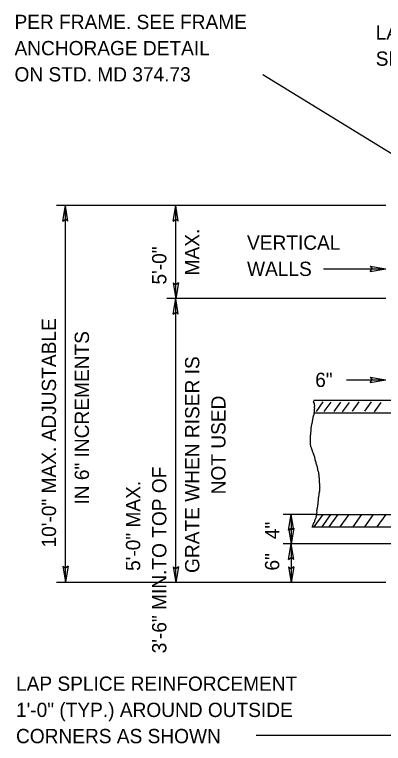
# Model space of a CAD drawing. Extents: x 9.6 to 16.8, y 2.2 to 12.2.
# Drawn here: x 9.55 to 11.1, y 6.199 to 9.259 of the extents above; entities that cross this region are included whole.
import ezdxf

# ---------------------------------------------------------------- set-up
doc = ezdxf.new("R2010")
doc.units = 0
for name, color, linetype in [('DETL-DIMS', 7, 'Continuous'), ('DETL-LINE', 7, 'Continuous'), ('DETL-NOTE', 7, 'Continuous'), ('DETL-PATT', 7, 'Continuous')]:
    doc.layers.add(name, color=color, linetype=linetype)

msp = doc.modelspace()

# ---------------------------------------------------------------- linework, layer by layer
at = {"layer": 'DETL-DIMS'}
for p, q in [((10.5932, 9.008), (11.2062, 8.6311)), ((11.1096, 8.4572), (9.7269, 8.4572)), ((9.7526, 8.3914), (9.7637, 8.4572)), ((9.7745, 8.3913), (9.7637, 8.4572)), ((9.7637, 6.8778), (9.7637, 8.4572)), ((10.2162, 8.3914), (10.2273, 8.4572)), ((10.2382, 8.3913), (10.2273, 8.4572)), ((10.2273, 8.0667), (10.2273, 8.4572)), ((9.7526, 8.3914), (9.7636, 8.3996)), ((9.7745, 8.3913), (9.7636, 8.3996)), ((10.2162, 8.3914), (10.2272, 8.3996)), ((10.2382, 8.3913), (10.2272, 8.3996)), ((11.0438, 8.2024), (11.1096, 8.1915)), ((11.0438, 8.2024), (11.052, 8.1915)), ((10.8477, 8.1915), (11.1096, 8.1915)), ((11.0438, 8.1805), (11.1096, 8.1915)), ((11.0438, 8.1805), (11.052, 8.1915)), ((10.2165, 8.1327), (10.2273, 8.0667)), ((10.2165, 8.1327), (10.2275, 8.1244)), ((10.2384, 8.1326), (10.2273, 8.0667)), ((10.2384, 8.1326), (10.2275, 8.1244)), ((11.1096, 8.0667), (10.1904, 8.0667)), ((10.2162, 8.0009), (10.2273, 8.0667)), ((10.2382, 8.0008), (10.2273, 8.0667)), ((10.2273, 6.8747), (10.2273, 8.0667)), ((10.2162, 8.0009), (10.2272, 8.0091)), ((10.2382, 8.0008), (10.2272, 8.0091)), ((10.9452, 7.7256), (11.1096, 7.7253)), ((11.0437, 7.7144), (11.052, 7.7254)), ((11.0437, 7.7144), (11.1096, 7.7253)), ((11.0438, 7.7364), (11.1096, 7.7253)), ((11.0438, 7.7364), (11.052, 7.7254)), ((10.8178, 7.1604), (10.6784, 7.1604)), ((10.7015, 7.0945), (10.7126, 7.1604)), ((10.7126, 7.1604), (10.7126, 7.0371)), ((10.7235, 7.0944), (10.7126, 7.1604)), ((10.7015, 7.0945), (10.7125, 7.1027)), ((10.7018, 7.1031), (10.7126, 7.0371)), ((10.7018, 7.1031), (10.7127, 7.0947)), ((10.7235, 7.0944), (10.7125, 7.1027)), ((10.7237, 7.103), (10.7126, 7.0371)), ((10.7237, 7.103), (10.7127, 7.0947)), ((11.3059, 7.0371), (10.6784, 7.0371)), ((10.7015, 6.9712), (10.7126, 7.0371)), ((10.7126, 7.0371), (10.7126, 6.8747)), ((10.7235, 6.9711), (10.7126, 7.0371)), ((10.7015, 6.9712), (10.7125, 6.9795)), ((10.7235, 6.9711), (10.7125, 6.9795)), ((9.7528, 6.9438), (9.7637, 6.8778)), ((9.7528, 6.9438), (9.7638, 6.9355)), ((9.7748, 6.9437), (9.7637, 6.8778)), ((9.7748, 6.9437), (9.7638, 6.9355)), ((10.2165, 6.9406), (10.2273, 6.8747)), ((10.2165, 6.9406), (10.2275, 6.9323)), ((10.2384, 6.9405), (10.2273, 6.8747)), ((10.2384, 6.9405), (10.2275, 6.9323)), ((10.7018, 6.9406), (10.7126, 6.8747)), ((10.7018, 6.9406), (10.7127, 6.9323)), ((10.7237, 6.9405), (10.7126, 6.8747)), ((10.7237, 6.9405), (10.7127, 6.9323)), ((11.1096, 6.8747), (9.7269, 6.8747)), ((10.5653, 6.2335), (11.1787, 6.2335))]:
    msp.add_line(p, q, dxfattribs=at)
at = {"layer": 'DETL-LINE'}
for p, q in [((10.8071, 7.6397), (11.3071, 7.6397)), ((10.8078, 7.5875), (11.3075, 7.5875)), ((10.8178, 7.1604), (11.3296, 7.1604)), ((10.7993, 7.1082), (11.3061, 7.1082))]:
    msp.add_line(p, q, dxfattribs=at)
for points in [[(10.806, 7.6325), (10.8062, 7.6318), (10.8062, 7.6299), (10.8081, 7.6285), (10.8095, 7.6275), (10.8091, 7.6271), (10.8095, 7.6224), (10.8095, 7.6096), (10.8099, 7.6068), (10.8095, 7.6026), (10.8095, 7.5955), (10.8085, 7.5899), (10.8071, 7.5852), (10.8071, 7.5776), (10.8052, 7.5739), (10.8042, 7.5696), (10.8038, 7.5687), (10.8038, 7.5673), (10.8028, 7.5626), (10.8014, 7.557), (10.8014, 7.5542), (10.8004, 7.5527), (10.8, 7.549), (10.7995, 7.5443), (10.7985, 7.5405), (10.7976, 7.5377), (10.7971, 7.5353), (10.7962, 7.5283), (10.7947, 7.5212), (10.7952, 7.5189), (10.7947, 7.5165), (10.7947, 7.5109), (10.7942, 7.5052), (10.7933, 7.4954), (10.7928, 7.4935), (10.7928, 7.4888), (10.7923, 7.485), (10.7923, 7.4723), (10.7918, 7.469), (10.7922, 7.4662), (10.7922, 7.4629), (10.7927, 7.4577), (10.7927, 7.4521), (10.7931, 7.4507), (10.7941, 7.4488), (10.7941, 7.446), (10.796, 7.4417), (10.7964, 7.4389), (10.7983, 7.4347), (10.7996, 7.4309), (10.8001, 7.429), (10.8011, 7.4257), (10.8025, 7.4234), (10.8048, 7.4163), (10.8062, 7.4135), (10.8071, 7.4107), (10.808, 7.4083), (10.8085, 7.4059), (10.8099, 7.4031), (10.8104, 7.4007), (10.8108, 7.3979), (10.8118, 7.3927), (10.8122, 7.3895), (10.8131, 7.3866), (10.8136, 7.3847), (10.8145, 7.3838), (10.8155, 7.3777), (10.8164, 7.3739), (10.8178, 7.3716), (10.8183, 7.3687), (10.8187, 7.3669), (10.8206, 7.3631), (10.8211, 7.3598), (10.8215, 7.3575), (10.8225, 7.3551), (10.8229, 7.3523), (10.8243, 7.3447), (10.8257, 7.3419), (10.8266, 7.3386), (10.8271, 7.333), (10.8271, 7.3311), (10.8289, 7.3217), (10.8289, 7.3193), (10.8294, 7.3132), (10.8298, 7.3071), (10.8303, 7.3043), (10.8298, 7.3015), (10.8303, 7.2986), (10.8307, 7.2939), (10.8307, 7.2897), (10.8312, 7.2864), (10.8312, 7.2793), (10.8316, 7.2779), (10.8321, 7.2737)], [(10.8067, 7.6379), (10.8062, 7.6341), (10.8062, 7.6318), (10.806, 7.6325)], [(10.8321, 7.2737), (10.8316, 7.269), (10.8307, 7.2568), (10.8302, 7.253), (10.8292, 7.2497), (10.8292, 7.245), (10.8287, 7.2422), (10.8278, 7.2375), (10.8264, 7.2285), (10.8254, 7.2253), (10.8254, 7.2196), (10.8245, 7.2135), (10.824, 7.2074), (10.824, 7.2027), (10.8235, 7.2008), (10.8235, 7.1989), (10.823, 7.1961), (10.823, 7.1947), (10.8225, 7.1924), (10.8216, 7.1858), (10.8206, 7.1811), (10.8206, 7.1792), (10.8202, 7.1792), (10.8201, 7.1707), (10.8192, 7.166), (10.8182, 7.1618), (10.8178, 7.1604), (10.8182, 7.1589), (10.8182, 7.1566), (10.8173, 7.1538), (10.8168, 7.1514), (10.8158, 7.1495), (10.8154, 7.1472), (10.8154, 7.1453), (10.8135, 7.1406), (10.8111, 7.1359), (10.8107, 7.134), (10.8102, 7.1293), (10.8064, 7.1246), (10.805, 7.1209), (10.8031, 7.1166), (10.8022, 7.1124), (10.8007, 7.1096), (10.7993, 7.1082)]]:
    msp.add_spline(points, degree=3, dxfattribs=at)
at = {"layer": 'DETL-PATT'}
for p, q in [((10.8184, 7.5931), (10.8466, 7.6326)), ((10.8516, 7.5922), (10.8799, 7.6316)), ((10.8929, 7.5921), (10.9211, 7.6316)), ((10.9285, 7.5915), (10.9567, 7.631)), ((10.9702, 7.5938), (10.9985, 7.6333)), ((11.0213, 7.5937), (11.0496, 7.6332)), ((11.0621, 7.5913), (11.0904, 7.6307)), ((10.8089, 7.1082), (10.8462, 7.1604)), ((10.8419, 7.1082), (10.8792, 7.1604)), ((10.872, 7.1082), (10.9093, 7.1604)), ((10.9185, 7.1082), (10.9558, 7.1604)), ((10.9721, 7.1082), (11.0094, 7.1604)), ((11.0214, 7.1082), (11.0587, 7.1604)), ((11.0738, 7.1082), (11.1112, 7.1604))]:
    msp.add_line(p, q, dxfattribs=at)

# ---------------------------------------------------------------- texts
at = {"layer": 'DETL-NOTE'}
for s, p in [('PER FRAME. SEE FRAME', (9.5501, 9.198)), ('ANCHORAGE DETAIL', (9.5501, 9.088)), ('ON STD. MD 374.73', (9.5501, 8.978)), ('VERTICAL', (10.5269, 8.2715)), ('WALLS', (10.5269, 8.1615)), ('6"', (10.8133, 7.6956)), ('LAP SPLICE REINFORCEMENT', (9.5564, 6.4201)), ('1\'-0" (TYP.) AROUND OUTSIDE', (9.5564, 6.3101)), ('CORNERS AS SHOWN', (9.5564, 6.2001))]:
    msp.add_text(s, height=0.06, dxfattribs=at).set_placement(p)
for s, rotation, p in [('LADDER RUNGS', 360, (11.0675, 9.1539)), ('SEE NOTE 7', 360, (11.0675, 9.0439)), ('MAX.', 90, (10.3265, 8.1637)), ('5\'-0"', 90, (10.1881, 8.1256)), ('10\'-0" MAX. ADJUSTABLE', 90, (9.7245, 7.0218)), ('IN 6" INCREMENTS', 90, (9.8629, 7.2018)), ('GRATE WHEN RISER IS', 90, (10.3265, 6.9149)), ('NOT USED', 90, (10.4365, 7.2447)), ('         3\'-6" MIN.TO TOP OF', 90, (10.188, 6.3768)), ('5\'-0" MAX.', 90, (10.078, 6.9233)), ('4"', 90, (10.6625, 7.0567)), ('6"', 90, (10.6623, 6.9249))]:
    msp.add_text(s, height=0.06, rotation=rotation, dxfattribs=at).set_placement(p)

doc.saveas('drawing.dxf')
